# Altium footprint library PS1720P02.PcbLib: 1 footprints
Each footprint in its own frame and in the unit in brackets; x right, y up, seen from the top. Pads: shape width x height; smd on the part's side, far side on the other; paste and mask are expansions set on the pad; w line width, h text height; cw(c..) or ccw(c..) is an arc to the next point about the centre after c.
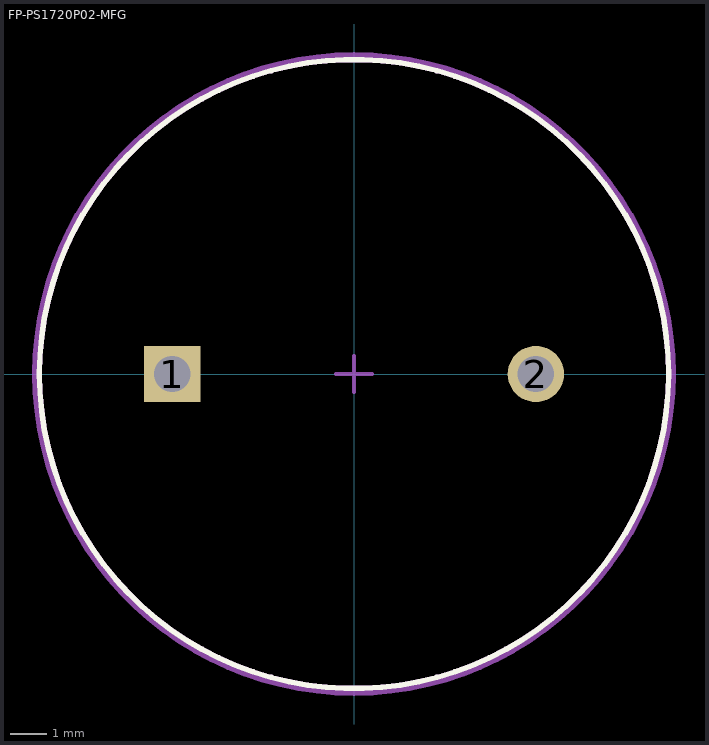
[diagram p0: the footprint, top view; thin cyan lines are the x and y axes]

## FP-PS1720P02-MFG [mm]
pads (2):
  rect 1.55x1.55 hole 1 paste-2539.97 mask+0: 1(-5,0)
  round 1.55 hole 1 paste-2539.97 mask+0: 2(5,0)
Top Overlay:
  circle w0.15: c0,0 r8.65
Top Assembly:
  text ".Designator" at 0,-0.001 h1
Top 3D Body:
  circle w0.15: c0,0 r8.65
Top Courtyard:
  lines w0.2: -8.75,0 ccw(c0,0) 8.75,0 ccw(c0,0) -8.75,0
Top Component Center:
  lines w0.1: -0.5,0 0.5,0 ; 0,-0.5 0,0.5
3D body "Speak_TDK_Corporation_PS1720P02_eec.STEP": height 0.25, standoff 0, extent -8.75,-8.75 8.75,8.75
